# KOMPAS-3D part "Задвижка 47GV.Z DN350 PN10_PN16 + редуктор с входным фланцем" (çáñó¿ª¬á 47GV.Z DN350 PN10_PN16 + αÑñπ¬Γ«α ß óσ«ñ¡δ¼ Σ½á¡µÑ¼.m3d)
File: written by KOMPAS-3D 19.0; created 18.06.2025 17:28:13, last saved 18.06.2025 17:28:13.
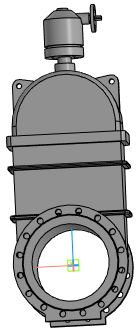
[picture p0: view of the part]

Document properties: Полное имя файла: Задвижка 47GV.Z DN350 PN10_PN16 + редуктор с входным фланцем.a3d

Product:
- Part/product: Задвижка 47GV.Z DN350 PN10_PN16 + редуктор с входным фланцем
    Масса: 564.615

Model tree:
1. Операция без истории:1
